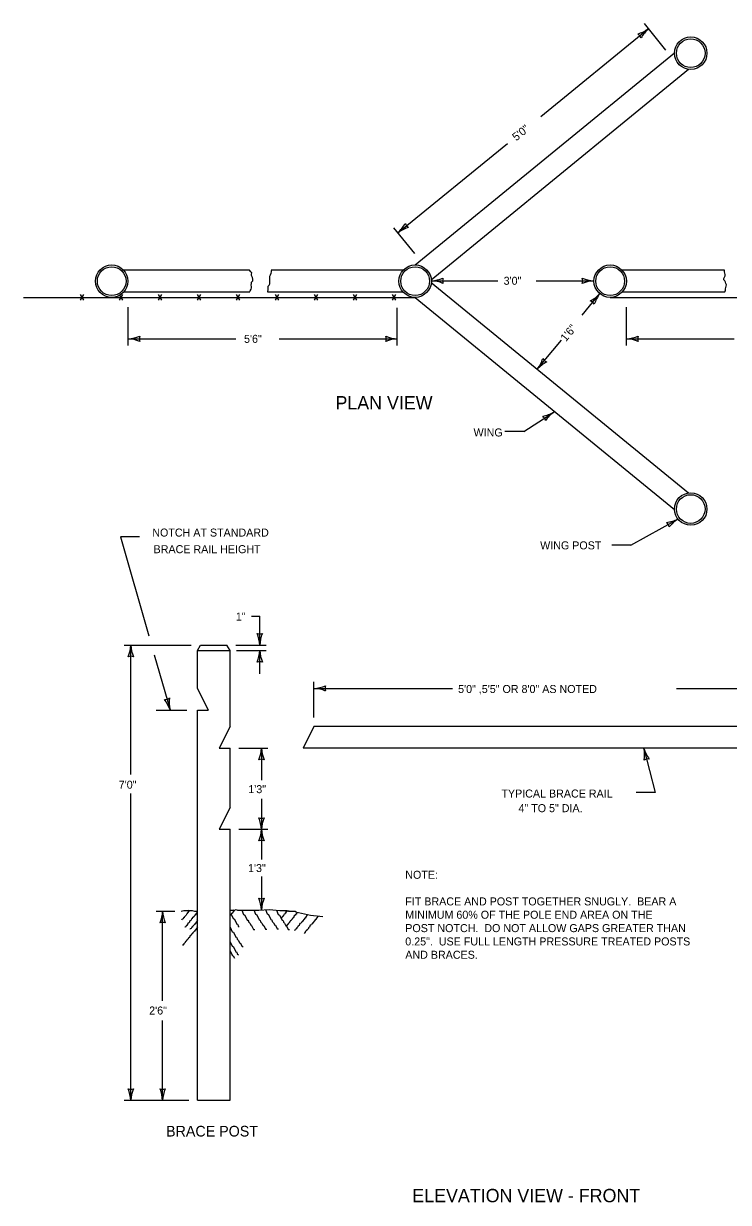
# Model space of a CAD drawing. Extents: x 49991 to 50288, y 49919 to 50011.
# Drawn here: x 50037 to 50047.9, y 49926.99 to 49945.22 of the extents above; entities that cross this region are included whole.
import ezdxf

# ---------------------------------------------------------------- set-up
doc = ezdxf.new("R2010")
doc.units = 0
for name, color, linetype in [('Level 1', 7, 'Continuous'), ('Level 2', 7, 'Continuous'), ('Level 3', 7, 'Continuous'), ('Level 5', 7, 'Continuous'), ('Level 7', 7, 'Continuous')]:
    doc.layers.add(name, color=color, linetype=linetype)

msp = doc.modelspace()

# ---------------------------------------------------------------- linework, layer by layer
at = {"layer": 'Level 1'}
for centre, radius, start, end in [((50046.35, 49945.566), 0.526, 286.4588, 306.6423), ((50046.428, 49944.953), 0.13, 21.1416, 56.8639), ((50047.032, 49944.733), 0.551, 131.8301, 151.0799), ((50042.417, 49942.394), 0.551, 312.2742, 331.524), ((50043.105, 49941.566), 0.526, 106.9029, 127.0864), ((50043.022, 49942.179), 0.13, 201.5857, 237.308), ((50043.279, 49941.796), 0.551, 272.8273, 292.0772), ((50043.284, 49940.719), 0.526, 67.456, 87.6395), ((50043.61, 49941.245), 0.13, 162.1388, 197.8612), ((50045.842, 49941.771), 0.526, 247.456, 267.6395), ((50045.517, 49941.245), 0.13, 342.1388, 17.8612), ((50045.848, 49940.694), 0.551, 92.8273, 112.0772), ((50045.523, 49941.4), 0.526, 297.4326, 317.6161), ((50046.351, 49940.712), 0.551, 142.8039, 162.0537), ((50045.716, 49940.813), 0.13, 32.1154, 67.8378), ((50038.589, 49940.898), 0.551, 272.8273, 292.0772), ((50038.595, 49939.821), 0.526, 67.456, 87.6395), ((50038.92, 49940.347), 0.13, 162.1388, 197.8612), ((50042.802, 49940.873), 0.526, 247.456, 267.6395), ((50042.477, 49940.347), 0.13, 342.1388, 17.8612), ((50042.807, 49939.796), 0.551, 92.8273, 112.0772), ((50046.299, 49940.898), 0.551, 272.8273, 292.0772), ((50046.305, 49939.821), 0.526, 67.456, 87.6395), ((50046.63, 49940.347), 0.13, 162.1388, 197.8612), ((50044.506, 49940.213), 0.551, 322.6318, 341.8817), ((50045.332, 49939.522), 0.526, 117.2605, 137.4441), ((50045.14, 49940.11), 0.13, 211.9434, 247.6657), ((50044.934, 49939.668), 0.526, 280.3051, 300.4886), ((50044.946, 49939.05), 0.13, 14.9879, 50.7103), ((50045.522, 49938.767), 0.551, 125.6764, 144.9263), ((50046.884, 49938.03), 0.526, 276.4524, 296.6359), ((50046.855, 49937.412), 0.13, 11.1352, 46.8576), ((50047.411, 49937.091), 0.551, 121.8237, 141.0736), ((50040.652, 49935.914), 0.13, 252.1388, 287.8612), ((50040.101, 49935.584), 0.551, 2.8273, 22.0772), ((50041.178, 49935.589), 0.526, 157.456, 177.6395), ((50038.132, 49935.633), 0.526, 337.456, 357.6395), ((50039.209, 49935.638), 0.551, 182.8273, 202.0772), ((50040.126, 49935.549), 0.526, 337.456, 357.6395), ((50041.203, 49935.555), 0.551, 182.8273, 202.0772), ((50038.658, 49935.307), 0.13, 72.1388, 107.8612), ((50040.652, 49935.224), 0.13, 72.1388, 107.8612), ((50041.462, 49935.491), 0.551, 272.8273, 292.0772), ((50041.793, 49934.941), 0.13, 162.1388, 197.8612), ((50039.181, 49934.9), 0.13, 268.1601, 303.8825), ((50038.743, 49934.431), 0.551, 18.8486, 38.0985), ((50039.777, 49934.733), 0.526, 173.4773, 193.6608), ((50041.468, 49934.415), 0.526, 67.456, 87.6395), ((50040.153, 49934.04), 0.526, 337.456, 357.6395), ((50041.229, 49934.046), 0.551, 182.8273, 202.0772), ((50046.079, 49933.91), 0.526, 351.2781, 11.4616), ((50047.123, 49934.172), 0.551, 196.6494, 215.8992), ((50040.679, 49933.715), 0.13, 72.1388, 107.8612), ((50046.667, 49933.72), 0.13, 85.9609, 121.6832), ((50040.679, 49933.065), 0.13, 252.1388, 287.8612), ((50040.128, 49932.734), 0.551, 2.8273, 22.0772), ((50041.204, 49932.74), 0.526, 157.456, 177.6395), ((50040.153, 49932.783), 0.526, 337.456, 357.6395), ((50041.229, 49932.789), 0.551, 182.8273, 202.0772), ((50040.679, 49932.458), 0.13, 72.1388, 107.8612), ((50040.679, 49931.819), 0.13, 252.1388, 287.8612), ((50040.128, 49931.489), 0.551, 2.8273, 22.0772), ((50041.204, 49931.494), 0.526, 157.456, 177.6395), ((50038.624, 49931.518), 0.526, 337.456, 357.6395), ((50039.7, 49931.523), 0.551, 182.8273, 202.0772), ((50039.149, 49931.193), 0.13, 72.1388, 107.8612), ((50038.658, 49928.874), 0.13, 252.1388, 287.8612), ((50038.107, 49928.543), 0.551, 2.8273, 22.0772), ((50039.184, 49928.549), 0.526, 157.456, 177.6395), ((50039.149, 49928.874), 0.13, 252.1388, 287.8612), ((50038.599, 49928.543), 0.551, 2.8273, 22.0772), ((50039.675, 49928.549), 0.526, 157.456, 177.6395)]:
    msp.add_arc(centre, radius, start, end, dxfattribs=at)
at = {"layer": 'Level 3'}
for p, q in [((50040.679, 49934.019), (50040.679, 49933.52)), ((50040.679, 49933.234), (50040.679, 49932.762)), ((50040.679, 49932.762), (50040.679, 49932.297)), ((50040.679, 49932.03), (50040.679, 49931.516))]:
    msp.add_line(p, q, dxfattribs=at)
at = {"layer": 'Level 5'}
msp.add_line((50041.046, 49931.5), (50041.107, 49931.5), dxfattribs=at)
for points in [[(50039.438, 49931.495), (50039.479, 49931.504), (50039.605, 49931.504), (50039.643, 49931.494), (50039.691, 49931.494)], [(50039.551, 49931.511), (50039.561, 49931.501), (50039.532, 49931.463), (50039.532, 49931.453), (50039.522, 49931.453), (50039.513, 49931.434), (50039.484, 49931.405), (50039.484, 49931.395), (50039.474, 49931.395), (50039.465, 49931.376), (50039.445, 49931.366), (50039.442, 49931.355)], [(50039.676, 49931.491), (50039.686, 49931.482), (50039.657, 49931.443), (50039.657, 49931.434), (50039.647, 49931.434), (50039.638, 49931.414), (50039.609, 49931.386), (50039.609, 49931.376), (50039.599, 49931.376), (50039.59, 49931.357), (50039.57, 49931.347), (50039.561, 49931.318), (50039.541, 49931.308), (50039.541, 49931.299), (50039.522, 49931.279), (50039.522, 49931.27), (50039.513, 49931.27), (50039.503, 49931.251), (50039.493, 49931.251), (50039.493, 49931.248)], [(50040.193, 49931.511), (50040.202, 49931.513), (50040.26, 49931.513), (50040.289, 49931.523), (50040.308, 49931.513), (50040.607, 49931.513), (50040.636, 49931.513), (50040.8, 49931.523), (50040.963, 49931.504), (50041.07, 49931.504), (50041.098, 49931.494), (50041.166, 49931.494), (50041.204, 49931.494), (50041.204, 49931.484), (50041.436, 49931.436), (50041.627, 49931.412)], [(50040.246, 49931.516), (50040.255, 49931.506), (50040.226, 49931.467), (50040.226, 49931.458), (50040.216, 49931.458), (50040.207, 49931.439), (50040.2, 49931.432)], [(50040.373, 49931.513), (50040.402, 49931.446), (50040.421, 49931.436), (50040.46, 49931.359), (50040.47, 49931.359), (50040.479, 49931.34), (50040.479, 49931.33), (50040.498, 49931.311), (50040.518, 49931.272), (50040.527, 49931.272), (50040.556, 49931.214), (50040.576, 49931.214)], [(50040.559, 49931.516), (50040.588, 49931.448), (50040.607, 49931.439), (50040.645, 49931.361), (50040.655, 49931.361), (50040.665, 49931.342), (50040.665, 49931.333), (50040.684, 49931.313), (50040.703, 49931.275), (50040.713, 49931.275), (50040.742, 49931.217), (50040.761, 49931.217)], [(50040.739, 49931.52), (50040.768, 49931.453), (50040.788, 49931.443), (50040.826, 49931.366), (50040.836, 49931.366), (50040.845, 49931.347), (50040.845, 49931.338), (50040.865, 49931.318), (50040.884, 49931.279), (50040.894, 49931.279), (50040.923, 49931.222), (50040.942, 49931.222)], [(50040.911, 49931.511), (50040.939, 49931.443), (50040.959, 49931.434), (50040.997, 49931.357), (50041.007, 49931.357), (50041.017, 49931.338), (50041.017, 49931.328), (50041.036, 49931.308), (50041.055, 49931.27), (50041.065, 49931.27), (50041.094, 49931.212), (50041.113, 49931.212)], [(50041.073, 49931.492), (50041.055, 49931.475), (50041.055, 49931.465), (50041.045, 49931.465), (50041.036, 49931.446), (50041.026, 49931.446), (50041.026, 49931.436), (50041.007, 49931.417), (50041.007, 49931.407), (50040.997, 49931.407), (50040.988, 49931.388)], [(50039.68, 49931.365), (50039.689, 49931.356), (50039.661, 49931.317), (50039.661, 49931.307), (50039.651, 49931.307), (50039.641, 49931.288), (50039.612, 49931.259), (50039.612, 49931.25), (50039.603, 49931.25), (50039.593, 49931.23), (50039.574, 49931.221), (50039.57, 49931.21)], [(50040.212, 49931.448), (50040.241, 49931.381), (50040.26, 49931.371), (50040.298, 49931.294), (50040.308, 49931.294), (50040.318, 49931.275), (50040.318, 49931.265), (50040.336, 49931.247)], [(50041.229, 49931.468), (50041.221, 49931.46), (50041.221, 49931.451), (50041.212, 49931.451), (50041.202, 49931.432), (50041.183, 49931.422), (50041.173, 49931.393), (50041.154, 49931.383), (50041.154, 49931.373), (50041.135, 49931.354), (50041.135, 49931.345), (50041.125, 49931.345), (50041.115, 49931.325), (50041.106, 49931.325), (50041.106, 49931.316), (50041.086, 49931.296), (50041.086, 49931.287), (50041.077, 49931.287), (50041.067, 49931.267)], [(50041.378, 49931.448), (50041.388, 49931.439), (50041.359, 49931.4), (50041.359, 49931.39), (50041.349, 49931.39), (50041.339, 49931.371), (50041.311, 49931.342), (50041.311, 49931.333), (50041.301, 49931.333), (50041.291, 49931.313), (50041.272, 49931.303), (50041.262, 49931.275), (50041.243, 49931.265), (50041.243, 49931.255), (50041.224, 49931.236), (50041.224, 49931.227), (50041.214, 49931.227), (50041.204, 49931.207), (50041.195, 49931.207), (50041.195, 49931.198), (50041.192, 49931.195)], [(50041.539, 49931.422), (50041.549, 49931.412), (50041.52, 49931.373), (50041.52, 49931.364), (50041.511, 49931.364), (50041.501, 49931.345), (50041.472, 49931.316), (50041.472, 49931.306), (50041.462, 49931.306), (50041.453, 49931.287), (50041.433, 49931.277), (50041.424, 49931.248), (50041.404, 49931.239), (50041.404, 49931.229), (50041.385, 49931.209), (50041.385, 49931.2), (50041.376, 49931.2), (50041.366, 49931.181), (50041.356, 49931.181), (50041.356, 49931.171), (50041.337, 49931.152)], [(50039.68, 49931.262), (50039.69, 49931.253), (50039.661, 49931.214), (50039.661, 49931.204), (50039.651, 49931.204), (50039.641, 49931.185), (50039.613, 49931.156), (50039.613, 49931.147), (50039.603, 49931.147), (50039.593, 49931.127), (50039.574, 49931.118), (50039.564, 49931.089), (50039.545, 49931.079), (50039.545, 49931.069), (50039.526, 49931.05), (50039.526, 49931.04), (50039.516, 49931.04), (50039.507, 49931.021), (50039.497, 49931.021), (50039.497, 49931.011), (50039.477, 49930.992), (50039.477, 49930.983), (50039.468, 49930.983), (50039.458, 49930.963)], [(50040.196, 49931.247), (50040.224, 49931.179), (50040.244, 49931.17), (50040.282, 49931.093), (50040.292, 49931.093), (50040.302, 49931.073), (50040.302, 49931.064), (50040.321, 49931.044), (50040.34, 49931.006), (50040.35, 49931.006), (50040.379, 49930.948), (50040.398, 49930.948)], [(50040.197, 49931.021), (50040.226, 49930.954), (50040.245, 49930.944), (50040.284, 49930.867), (50040.293, 49930.867), (50040.303, 49930.848), (50040.303, 49930.838), (50040.321, 49930.821)], [(50040.194, 49930.881), (50040.223, 49930.814), (50040.243, 49930.804), (50040.261, 49930.767)]]:
    msp.add_lwpolyline(points, dxfattribs=at)
at = {"layer": 'Level 7'}
for p, q in [((50046.934, 49944.813), (50046.601, 49945.222)), ((50044.998, 49943.786), (50046.664, 49945.144)), ((50043.057, 49941.491), (50047.067, 49944.771)), ((50043.305, 49941.26), (50047.284, 49944.515)), ((50042.788, 49941.986), (50044.482, 49943.366)), ((50043.05, 49941.665), (50042.725, 49942.064)), ((50040.495, 49941.407), (50038.55, 49941.407)), ((50042.868, 49941.407), (50040.828, 49941.407)), ((50047.841, 49941.407), (50046.259, 49941.407)), ((50043.305, 49941.219), (50047.284, 49937.964)), ((50043.306, 49941.245), (50044.334, 49941.245)), ((50044.928, 49941.245), (50045.821, 49941.245)), ((50036.999, 49940.988), (50043.057, 49940.988)), ((50037.879, 49940.944), (50037.929, 49941.031)), ((50037.929, 49940.944), (50037.879, 49941.031)), ((50038.483, 49940.944), (50038.533, 49941.031)), ((50038.533, 49940.944), (50038.483, 49941.031)), ((50040.492, 49941.071), (50038.55, 49941.071)), ((50039.086, 49940.944), (50039.136, 49941.031)), ((50039.136, 49940.944), (50039.086, 49941.031)), ((50039.69, 49940.944), (50039.74, 49941.031)), ((50039.74, 49940.944), (50039.69, 49941.031)), ((50040.293, 49940.944), (50040.343, 49941.031)), ((50040.343, 49940.944), (50040.293, 49941.031)), ((50042.868, 49941.071), (50040.778, 49941.071)), ((50040.896, 49940.944), (50040.947, 49941.031)), ((50040.947, 49940.944), (50040.896, 49941.031)), ((50041.5, 49940.944), (50041.55, 49941.031)), ((50041.55, 49940.944), (50041.5, 49941.031)), ((50042.103, 49940.944), (50042.154, 49941.031)), ((50042.154, 49940.944), (50042.103, 49941.031)), ((50042.707, 49940.944), (50042.757, 49941.031)), ((50042.757, 49940.944), (50042.707, 49941.031)), ((50043.057, 49940.988), (50047.067, 49937.708)), ((50045.637, 49940.714), (50045.912, 49941.046)), ((50046.071, 49940.985), (50050.764, 49940.985)), ((50047.841, 49941.071), (50046.259, 49941.071)), ((50038.617, 49940.246), (50038.617, 49940.835)), ((50042.78, 49940.246), (50042.78, 49940.825)), ((50046.326, 49940.246), (50046.326, 49940.835)), ((50038.617, 49940.347), (50040.282, 49940.347)), ((50040.952, 49940.347), (50042.78, 49940.347)), ((50044.944, 49939.878), (50045.317, 49940.328)), ((50046.326, 49940.347), (50047.992, 49940.347)), ((50044.734, 49938.913), (50045.201, 49939.215)), ((50044.734, 49938.913), (50044.441, 49938.913)), ((50046.392, 49937.157), (50047.12, 49937.559)), ((50038.79, 49937.284), (50038.497, 49937.284)), ((50038.497, 49937.284), (50038.937, 49935.752)), ((50046.392, 49937.157), (50046.098, 49937.157)), ((50040.522, 49936.06), (50040.652, 49936.06)), ((50040.652, 49935.611), (50040.652, 49936.06)), ((50038.557, 49935.611), (50039.591, 49935.611)), ((50038.658, 49933.609), (50038.658, 49935.611)), ((50039.69, 49935.527), (50039.738, 49935.611)), ((50039.69, 49935.527), (50040.192, 49935.527)), ((50039.69, 49934.94), (50039.69, 49935.527)), ((50039.738, 49935.611), (50040.144, 49935.611)), ((50040.192, 49935.527), (50040.144, 49935.611)), ((50040.192, 49934.354), (50040.192, 49935.527)), ((50040.281, 49935.611), (50040.752, 49935.611)), ((50040.291, 49935.527), (50040.752, 49935.527)), ((50040.652, 49935.167), (50040.652, 49935.527)), ((50039.021, 49935.461), (50039.265, 49934.609)), ((50041.489, 49934.492), (50041.489, 49935.041)), ((50039.69, 49934.94), (50039.856, 49934.605)), ((50041.489, 49934.941), (50043.633, 49934.941)), ((50047.1, 49934.941), (50049.201, 49934.941)), ((50039.049, 49934.605), (50039.522, 49934.605)), ((50039.69, 49934.605), (50039.856, 49934.605)), ((50039.69, 49928.571), (50039.69, 49934.605)), ((50040.192, 49934.354), (50040.025, 49934.019)), ((50041.489, 49934.354), (50041.322, 49934.019)), ((50049.201, 49934.354), (50041.489, 49934.354)), ((50040.025, 49934.019), (50040.192, 49934.019)), ((50040.192, 49933.097), (50040.192, 49934.019)), ((50040.328, 49934.019), (50040.779, 49934.019)), ((50049.368, 49934.019), (50041.322, 49934.019)), ((50046.594, 49934.014), (50046.767, 49933.329)), ((50038.658, 49928.571), (50038.658, 49933.318)), ((50046.767, 49933.329), (50046.473, 49933.329)), ((50040.192, 49933.097), (50040.025, 49932.762)), ((50040.025, 49932.762), (50040.192, 49932.762)), ((50040.192, 49928.571), (50040.192, 49932.762)), ((50040.328, 49932.762), (50040.779, 49932.762)), ((50039.049, 49931.496), (50039.339, 49931.496)), ((50039.149, 49930.111), (50039.149, 49931.496)), ((50039.149, 49928.571), (50039.149, 49929.805)), ((50038.557, 49928.571), (50039.556, 49928.571)), ((50039.69, 49928.571), (50040.192, 49928.571))]:
    msp.add_line(p, q, dxfattribs=at)
for points in [[(50040.492, 49941.071), (50040.505, 49941.088), (50040.519, 49941.115), (50040.524, 49941.135), (50040.522, 49941.157), (50040.519, 49941.179), (50040.522, 49941.202), (50040.527, 49941.224), (50040.547, 49941.244), (50040.547, 49941.268), (50040.539, 49941.295), (50040.524, 49941.325), (50040.527, 49941.347), (50040.529, 49941.369), (50040.514, 49941.384), (50040.495, 49941.407), (50040.495, 49941.407)], [(50040.778, 49941.071), (50040.781, 49941.115), (50040.781, 49941.14), (50040.783, 49941.162), (50040.798, 49941.179), (50040.806, 49941.199), (50040.808, 49941.221), (50040.81, 49941.246), (50040.808, 49941.271), (50040.806, 49941.293), (50040.806, 49941.318), (50040.818, 49941.335), (50040.828, 49941.364), (50040.833, 49941.384), (50040.833, 49941.404)], [(50047.841, 49941.071), (50047.854, 49941.088), (50047.854, 49941.119), (50047.863, 49941.139), (50047.868, 49941.16), (50047.869, 49941.182), (50047.86, 49941.202), (50047.854, 49941.223), (50047.844, 49941.244), (50047.831, 49941.26), (50047.831, 49941.282), (50047.839, 49941.303), (50047.852, 49941.32), (50047.849, 49941.341), (50047.843, 49941.363), (50047.838, 49941.384), (50047.84, 49941.405), (50047.841, 49941.407)], [(50037.603, 49940.988), (50037.854, 49940.988)], [(50037.955, 49940.988), (50038.206, 49940.988)], [(50038.206, 49940.988), (50038.458, 49940.988)], [(50038.558, 49940.988), (50038.81, 49940.988)], [(50038.81, 49940.988), (50039.061, 49940.988)], [(50039.162, 49940.988), (50039.413, 49940.988)], [(50039.413, 49940.988), (50039.664, 49940.988)], [(50039.765, 49940.988), (50040.016, 49940.988)], [(50040.016, 49940.988), (50040.268, 49940.988)], [(50040.368, 49940.988), (50040.62, 49940.988)], [(50040.62, 49940.988), (50040.871, 49940.988)], [(50040.972, 49940.988), (50041.223, 49940.988)], [(50041.223, 49940.988), (50041.475, 49940.988)], [(50041.575, 49940.988), (50041.827, 49940.988)], [(50041.827, 49940.988), (50042.078, 49940.988)], [(50042.179, 49940.988), (50042.43, 49940.988)], [(50042.43, 49940.988), (50042.682, 49940.988)], [(50042.782, 49940.988), (50043.034, 49940.988)], [(50043.034, 49940.988), (50043.057, 49940.988)]]:
    msp.add_lwpolyline(points, dxfattribs=at)
for centre, radius in [((50047.318, 49944.764), 0.251), ((50047.318, 49944.764), 0.222), ((50038.362, 49941.239), 0.251), ((50038.362, 49941.239), 0.222), ((50043.055, 49941.239), 0.251), ((50043.055, 49941.239), 0.222), ((50046.072, 49941.239), 0.251), ((50046.072, 49941.239), 0.222), ((50047.318, 49937.715), 0.251), ((50047.318, 49937.715), 0.222)]:
    msp.add_circle(centre, radius, dxfattribs=at)

# ---------------------------------------------------------------- texts
at = {"layer": 'Level 2'}
for s, height, rotation, p in [('5\'0"', 0.1237, 38.8845, (50044.619, 49943.4)), ('3\'0"', 0.1237, 360, (50044.424, 49941.183)), ('1\'6"', 0.1237, 50.4638, (50045.387, 49940.294)), ('5\'6"', 0.1237, 360, (50040.409, 49940.285)), ('1"', 0.1237, 360, (50040.282, 49935.99)), ('5\'0" ,5\'5" OR 8\'0" AS NOTED', 0.12374, 360, (50043.72, 49934.87)), ('7\'0"', 0.1237, 360, (50038.471, 49933.39)), ('1\'3"', 0.1237, 360, (50040.475, 49933.321)), ('1\'3"', 0.1237, 360, (50040.471, 49932.101)), ('2\'6"', 0.1237, 360, (50038.942, 49929.898))]:
    msp.add_text(s, height=height, rotation=rotation, dxfattribs=at).set_placement(p)
for s, height, p in [('PLAN VIEW', 0.2062, (50041.823, 49939.255)), ('WING', 0.1237, (50043.959, 49938.837)), ('NOTCH AT STANDARD', 0.12374, (50038.99, 49937.289)), ('BRACE RAIL HEIGHT', 0.12374, (50039.01, 49937.032)), ('WING POST', 0.1237, (50044.989, 49937.091)), ('TYPICAL BRACE RAIL', 0.12374, (50044.39, 49933.253)), ('4" TO 5" DIA.', 0.12374, (50044.654, 49933.027)), ('BRACE POST', 0.165, (50039.203, 49928.011)), ('ELEVATION VIEW - FRONT', 0.20623, (50043.012, 49926.995))]:
    msp.add_text(s, height=height, dxfattribs=at).set_placement(p)
at = {"layer": 'Level 5'}
for s, height, p in [('NOTE:', 0.1237, (50042.903, 49931.997)), ('FIT BRACE AND POST TOGETHER SNUGLY.  BEAR A', 0.12374, (50042.903, 49931.585)), ('MINIMUM 60% OF THE POLE END AREA ON THE ', 0.12374, (50042.903, 49931.379)), ('POST NOTCH.  DO NOT ALLOW GAPS GREATER THAN', 0.12374, (50042.903, 49931.172)), ('0.25".  USE FULL LENGTH PRESSURE TREATED POSTS', 0.12374, (50042.903, 49930.966)), ('AND BRACES.', 0.12374, (50042.903, 49930.76))]:
    msp.add_text(s, height=height, dxfattribs=at).set_placement(p)

doc.saveas('drawing.dxf')
